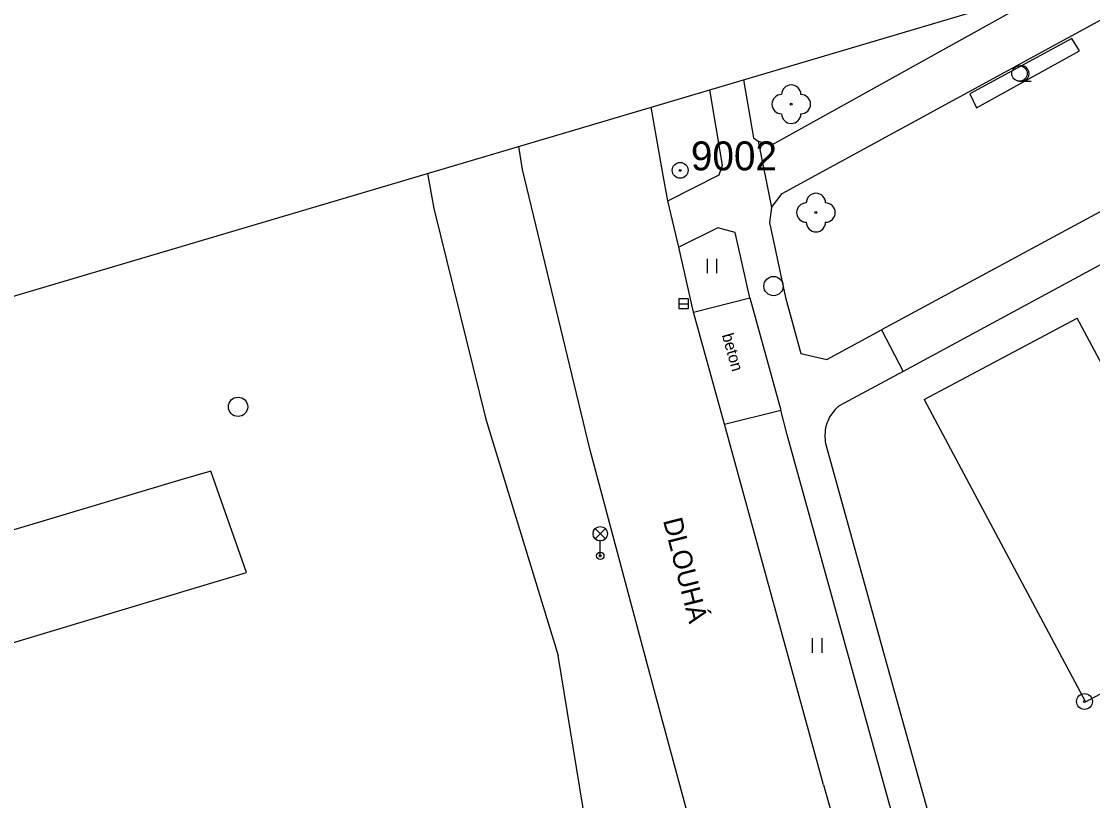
# Model space of a CAD drawing. Extents: x -493753 to -49290, y -1127285 to -112654.
# Drawn here: x -493575.9 to -493520.4, y -1126747.4 to -1126707 of the extents above; entities that cross this region are included whole.
import ezdxf

# ---------------------------------------------------------------- set-up
doc = ezdxf.new("R2010")
doc.units = 0
for name, color, linetype in [('Vrstva 1', 7, 'Continuous'), ('Vrstva 10', 7, 'Continuous'), ('Vrstva 11', 7, 'Continuous'), ('Vrstva 14', 7, 'Continuous'), ('Vrstva 21', 7, 'Continuous'), ('Vrstva 22', 7, 'Continuous'), ('Vrstva 27', 7, 'Continuous'), ('Vrstva 33', 7, 'Continuous'), ('Vrstva 36', 7, 'Continuous'), ('Vrstva 40', 7, 'Continuous'), ('Vrstva 45', 7, 'Continuous'), ('Vrstva 5', 7, 'Continuous'), ('Vrstva 60', 7, 'Continuous'), ('Vrstva 63', 7, 'Continuous')]:
    doc.layers.add(name, color=color, linetype=linetype)

msp = doc.modelspace()

# ---------------------------------------------------------------- linework, layer by layer
at = {"layer": 'Vrstva 1'}
msp.add_line((-492950.39, -1126535.73), (-493753.129, -1126773.634), dxfattribs=at)
at = {"layer": 'Vrstva 10'}
for p, q in [((-493538.479, -1126710.019), (-493537.96, -1126713.03)), ((-493539.57, -1126714.44), (-493540.237, -1126710.54)), ((-493537.96, -1126713.03), (-493537.73, -1126713.2)), ((-493549.94, -1126714.67), (-493550.134, -1126713.474)), ((-493546.44, -1126729.22), (-493549.94, -1126714.67)), ((-493539.75, -1126714.95), (-493539.57, -1126714.44)), ((-493542.4, -1126716.29), (-493539.75, -1126714.95)), ((-493537.03, -1126716.64), (-493536.48, -1126715.91)), ((-493537.03, -1126716.64), (-493537.14, -1126717.42)), ((-493539.82, -1126717.69), (-493541.84, -1126718.69)), ((-493538.92, -1126717.93), (-493539.82, -1126717.69)), ((-493537.14, -1126717.42), (-493536.3, -1126721.31)), ((-493538.15, -1126721.32), (-493538.92, -1126717.93)), ((-493541.07, -1126722.06), (-493538.15, -1126721.32)), ((-493536.3, -1126721.31), (-493535.52, -1126724.2)), ((-493534.16, -1126724.52), (-493531.34, -1126722.98)), ((-493535.52, -1126724.2), (-493534.16, -1126724.52)), ((-493530.21, -1126725.14), (-493533.52, -1126726.92)), ((-493533.74, -1126727.11), (-493534.02, -1126727.49)), ((-493533.65, -1126727.03), (-493533.74, -1126727.11)), ((-493533.57, -1126726.95), (-493533.65, -1126727.03)), ((-493533.57, -1126726.95), (-493533.52, -1126726.92)), ((-493539.47, -1126727.87), (-493536.55, -1126727.15)), ((-493536.22, -1126728.42), (-493536.55, -1126727.15)), ((-493534.07, -1126727.6), (-493534.12, -1126727.71)), ((-493534.02, -1126727.49), (-493534.07, -1126727.6)), ((-493534.25, -1126728.18), (-493534.26, -1126728.3)), ((-493534.23, -1126728.06), (-493534.25, -1126728.18)), ((-493534.2, -1126727.94), (-493534.23, -1126728.06)), ((-493534.16, -1126727.82), (-493534.2, -1126727.94)), ((-493534.12, -1126727.71), (-493534.16, -1126727.82)), ((-493532.39, -1126742.27), (-493536.22, -1126728.42)), ((-493534.26, -1126728.3), (-493534.27, -1126728.42)), ((-493534.27, -1126728.42), (-493534.27, -1126728.53)), ((-493534.27, -1126728.53), (-493534.26, -1126728.65)), ((-493534.26, -1126728.65), (-493534.25, -1126728.77)), ((-493534.25, -1126728.77), (-493534.23, -1126728.88)), ((-493542.98, -1126742.16), (-493546.44, -1126729.22)), ((-493534.23, -1126728.88), (-493534.2, -1126728.99)), ((-493534.2, -1126728.99), (-493530.66, -1126741.76)), ((-493530.66, -1126741.76), (-493525.89, -1126758.89)), ((-493528.51, -1126756.27), (-493532.39, -1126742.27)), ((-493534.33, -1126746.57), (-493530.75, -1126759.17))]:
    msp.add_line(p, q, dxfattribs=at)
for points in [[(-493536.48, -1126715.91), (-493512.82, -1126703), (-493510.426, -1126701.705)], [(-493537.73, -1126713.2), (-493537.02, -1126713.39), (-493524.35, -1126706.35)], [(-493488.99, -1126709.41), (-493500.28, -1126715.49), (-493512.45, -1126712.78), (-493531.34, -1126722.98)], [(-493542.4, -1126716.29), (-493542.67, -1126714.88), (-493543.265, -1126711.438)], [(-493541.84, -1126718.69), (-493542.4, -1126716.29)], [(-493541.07, -1126722.06), (-493541.84, -1126718.69)], [(-493519.67, -1126719.43), (-493530.21, -1126725.14)], [(-493534.33, -1126746.57), (-493539.47, -1126727.87), (-493541.07, -1126722.06)], [(-493537.92, -1126760.89), (-493538.35, -1126759.3), (-493542.98, -1126742.16)]]:
    msp.add_lwpolyline(points, dxfattribs=at)
at = {"layer": 'Vrstva 11'}
for p, q in [((-493537.73, -1126713.2), (-493537.03, -1126716.64)), ((-493538.15, -1126721.32), (-493536.55, -1126727.15)), ((-493531.34, -1126722.98), (-493530.21, -1126725.14))]:
    msp.add_line(p, q, dxfattribs=at)
for points in [[(-493566.1, -1126730.3), (-493567.66, -1126730.75), (-493602.36, -1126741.14)], [(-493564.25, -1126735.56), (-493566.1, -1126730.3)], [(-493600.92, -1126746.58), (-493566.8, -1126736.33), (-493564.25, -1126735.56)]]:
    msp.add_lwpolyline(points, dxfattribs=at)
at = {"layer": 'Vrstva 14'}
for points in [[(-493554.868, -1126714.877), (-493554.54, -1126716.69), (-493551.84, -1126727.61), (-493548.1, -1126739.86)], [(-493560.4, -1126765.56), (-493553.34, -1126764.02), (-493544.82, -1126761.32), (-493545.87, -1126753.49), (-493548.1, -1126739.86)]]:
    msp.add_lwpolyline(points, dxfattribs=at)
at = {"layer": 'Vrstva 21'}
for p, q in [((-493521.46, -1126707.88), (-493526.75, -1126710.74)), ((-493521.06, -1126708.51), (-493521.46, -1126707.88)), ((-493526.4, -1126711.47), (-493521.06, -1126708.51)), ((-493526.75, -1126710.74), (-493526.4, -1126711.47))]:
    msp.add_line(p, q, dxfattribs=at)
at = {"layer": 'Vrstva 22'}
for centre in [(-493536.01, -1126711.28), (-493534.73, -1126716.9)]:
    msp.add_circle(centre, 0.05, dxfattribs=at)
for centre, start, end in [((-493536.01, -1126710.78), 0, 180), ((-493536.51, -1126711.28), 90, 270), ((-493535.51, -1126711.28), 270, 90), ((-493536.01, -1126711.78), 180, 0), ((-493534.73, -1126716.4), 0, 180), ((-493535.23, -1126716.9), 90, 270), ((-493534.23, -1126716.9), 270, 90), ((-493534.73, -1126717.4), 180, 0)]:
    msp.add_arc(centre, 0.5, start, end, dxfattribs=at)
at = {"layer": 'Vrstva 27'}
msp.add_line((-493541.83, -1126721.63), (-493541.33, -1126721.63), dxfattribs=at)
msp.add_lwpolyline([(-493541.83, -1126721.88), (-493541.33, -1126721.88), (-493541.33, -1126721.38), (-493541.83, -1126721.38)], close=True, dxfattribs=at)
for centre in [(-493536.93, -1126720.71), (-493564.69, -1126726.97)]:
    msp.add_circle(centre, 0.5, dxfattribs=at)
at = {"layer": 'Vrstva 33'}
for p, q in [((-493546.175, -1126733.285), (-493545.645, -1126733.815)), ((-493546.175, -1126733.815), (-493545.645, -1126733.285)), ((-493545.91, -1126734.7), (-493545.91, -1126733.925))]:
    msp.add_line(p, q, dxfattribs=at)
for centre, radius in [((-493545.91, -1126733.55), 0.375), ((-493545.91, -1126734.7), 0.19), ((-493545.91, -1126734.7), 0.05)]:
    msp.add_circle(centre, radius, dxfattribs=at)
at = {"layer": 'Vrstva 36'}
for p, q in [((-493524.18, -1126710.09), (-493524.08, -1126710.09)), ((-493524.08, -1126710.09), (-493523.58, -1126710.09)), ((-493540.36, -1126720.04), (-493540.36, -1126719.29)), ((-493539.86, -1126720.04), (-493539.86, -1126719.29)), ((-493534.91, -1126739.72), (-493534.91, -1126738.97)), ((-493534.41, -1126739.72), (-493534.41, -1126738.97))]:
    msp.add_line(p, q, dxfattribs=at)
msp.add_circle((-493524.18, -1126709.69), 0.4, dxfattribs=at)
msp.add_arc((-493524.08, -1126709.69), 0.4, 259.6952, 97.1808, dxfattribs=at)
at = {"layer": 'Vrstva 5'}
for p in [(-493529.12, -1126726.6), (-493518.98, -1126726.51)]:
    msp.add_line(p, (-493521.19, -1126722.37), dxfattribs=at)
msp.add_lwpolyline([(-493529.12, -1126726.6), (-493520.75, -1126742.26), (-493502.71, -1126732.63)], dxfattribs=at)
at = {"layer": 'Vrstva 60'}
msp.add_line((-493125, -1126587.478), (-493750, -1126772.707), dxfattribs=at)
at = {"layer": 'Vrstva 63'}
for centre, radius in [((-493541.77, -1126714.71), 0.412), ((-493541.77, -1126714.71), 0.05), ((-493520.81, -1126742.25), 0.412), ((-493520.81, -1126742.25), 0.05)]:
    msp.add_circle(centre, radius, dxfattribs=at)

# ---------------------------------------------------------------- texts
at = {"layer": 'Vrstva 40'}
msp.add_text('beton', height=0.6, rotation=286.0054, dxfattribs=at).set_placement((-493539.613, -1126723.252))
at = {"layer": 'Vrstva 45'}
msp.add_text('DLOUHÁ', height=1, rotation=284.2308, dxfattribs=at).set_placement((-493542.664, -1126732.856))
at = {"layer": 'Vrstva 63'}
msp.add_text(' 9002', height=1.5, dxfattribs=at).set_placement((-493541.77, -1126714.71))

doc.saveas('drawing.dxf')
